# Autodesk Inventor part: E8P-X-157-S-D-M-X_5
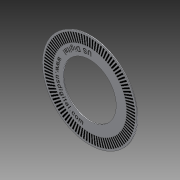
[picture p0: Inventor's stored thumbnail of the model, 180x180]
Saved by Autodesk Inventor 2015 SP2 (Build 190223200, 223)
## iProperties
Created: 2012-07
Part Number: E8P-X-157-S-D-M-X_5
Material: Allgemein
Document SubType Name: Modeling
Designer: rYan
Density: 1 g/cm^3
Mass: 0.0490807 g
Surface Area: 5.89347 cm^2
Volume: 0.0490807 cm^3
Appearance: Vorgabe
Author: rYan
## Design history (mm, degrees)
node "E8P-X-157-S-D-M-X_51"
node "E8P-X-157-S-D-M-X_5"
node "Basis1"
